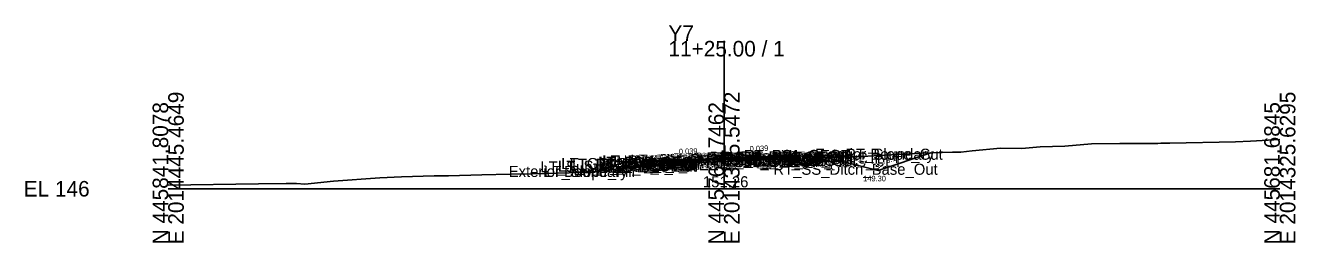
# Model space of a CAD drawing. Extents: x -26 to 203, y -10 to 7527.
# Drawn here: x -25.7 to 202.8, y 2490.3 to 2529.4 of the extents above; entities that cross this region are included whole.
import ezdxf

# ---------------------------------------------------------------- set-up
doc = ezdxf.new("R2010")
doc.units = 0
for name, color, linetype in [('Exist CMT Pavement', 7, 'Continuous'), ('Exist Cross Section Cell', 7, 'Continuous'), ('Exist XS Center Line Elevation Label', 7, 'Continuous'), ('Exist XS Ground Line', 7, 'Continuous'), ('Prop CMT Pvmt Course 1', 7, 'Continuous'), ('Prop CMT Pvmt Course 1 Wedge', 7, 'Continuous'), ('Prop CMT Pvmt Course 2', 7, 'Continuous'), ('Prop CMT Pvmt Course 2 Wedge', 7, 'Continuous'), ('Prop CMT Pvmt Course 3', 7, 'Continuous'), ('Prop CMT Pvmt Course 3 Wedge', 7, 'Continuous'), ('Prop CMT Pvmt Surface', 7, 'Continuous'), ('Prop CMT Pvmt Surface Shoulder', 7, 'Continuous'), ('Prop CMT Pvmt Wedge Surface 1', 7, 'Continuous'), ('Prop CMT Pvmt Wedge Surface 2', 7, 'Continuous'), ('Prop CMT Pvmt Wedge Surface 3', 7, 'Continuous'), ('Prop CMT Shld Paved Course 1', 7, 'Continuous'), ('Prop CMT Shld Paved Course 2', 7, 'Continuous'), ('Prop CMT Shld Paved Course 3', 7, 'Continuous'), ('Prop CMT Slope Grass', 7, 'Continuous'), ('Prop CMT Subgrade Earthwork', 7, 'Continuous'), ('Prop XS Ditch Standard Text', 7, 'Continuous'), ('Prop XS Earthwork Shape', 7, 'Continuous'), ('Prop XS SE Text', 7, 'Continuous'), ('Prop XS Side Slope Text', 7, 'Continuous'), ('Prop XS Wedging', 7, 'Continuous'), ('Scratch_Level_0', 7, 'Continuous')]:
    doc.layers.add(name, color=color, linetype=linetype)

msp = doc.modelspace()

# ---------------------------------------------------------------- linework, layer by layer
at = {"layer": 'Exist CMT Pavement'}
msp.add_lwpolyline([(93.3, 2505.03), (93.3, 2505.03), (93.89, 2505.04), (100, 2505.26), (100.81, 2505.28), (102.83, 2505.29), (107.59, 2505.3)], dxfattribs=at)
at = {"layer": 'Exist Cross Section Cell'}
for p, q in [((100, 2500), (100, 2526.62)), ((0, 2500), (100, 2500)), ((100, 2500), (200, 2500))]:
    msp.add_line(p, q, dxfattribs=at)
at = {"layer": 'Exist XS Ground Line'}
msp.add_lwpolyline([(0, 2500.67), (16.26, 2500.87), (21.22, 2500.96), (23.07, 2500.96), (24.6, 2500.84), (29.75, 2501.4), (38.09, 2501.97), (42, 2502.15), (47.86, 2502.31), (50.45, 2502.34), (56.42, 2502.49), (61.55, 2502.61), (65.4, 2502.71), (72.12, 2502.87), (75.6, 2502.95), (88.94, 2504.55), (91.24, 2504.8), (93.3, 2505.03), (93.89, 2505.04), (100, 2505.26), (100.81, 2505.28), (102.83, 2505.29), (107.59, 2505.3), (108.66, 2505.45), (111.02, 2505.83), (114.09, 2504.44), (114.73, 2504.22), (116.89, 2504.24), (118.03, 2505.23), (118.42, 2505.63), (124.81, 2505.79), (135.48, 2506.41), (141.1, 2506.6), (142.62, 2506.62), (144.65, 2506.82), (149.77, 2507.33), (153.59, 2507.28), (156.91, 2507.56), (161.35, 2507.7), (166.09, 2508.08), (171.2, 2508.13), (178.04, 2508.18), (178.58, 2508.19), (180.19, 2508.22), (192.01, 2508.44), (194.73, 2508.59), (200, 2508.87)], dxfattribs=at)
at = {"layer": 'Prop CMT Pvmt Course 1'}
for points in [[(100, 2505.51), (87.35, 2505.02)], [(87.35, 2505.02), (87.35, 2504.77)], [(87.35, 2504.77), (93.3, 2505)], [(93.3, 2505.12), (100, 2505.38)], [(93.3, 2505), (93.3, 2505.12)], [(100, 2505.51), (112.84, 2506)], [(107.59, 2505.67), (100, 2505.38)], [(100, 2505.26), (100, 2505.51)], [(100, 2505.26), (100, 2505.51)], [(100, 2505.38), (100, 2505.26), (100, 2505.26)], [(100, 2505.38), (100, 2505.26), (100, 2505.26)], [(112.84, 2505.75), (107.59, 2505.55)], [(107.59, 2505.55), (107.59, 2505.67)], [(112.84, 2506), (112.84, 2505.75)]]:
    msp.add_lwpolyline(points, dxfattribs=at)
at = {"layer": 'Prop CMT Pvmt Course 1 Wedge'}
for points in [[(100, 2505.38), (93.3, 2505.12)], [(100, 2505.38), (107.59, 2505.67)]]:
    msp.add_lwpolyline(points, dxfattribs=at)
at = {"layer": 'Prop CMT Pvmt Course 2'}
for points in [[(93.3, 2505), (87.35, 2504.77)], [(87.35, 2504.77), (87.35, 2504.43)], [(93.3, 2504.66), (93.3, 2505)], [(107.59, 2505.55), (112.84, 2505.75)], [(107.59, 2505.22), (107.59, 2505.55)], [(112.84, 2505.42), (107.59, 2505.22)], [(112.84, 2505.75), (112.84, 2505.42)], [(87.35, 2504.43), (93.3, 2504.66)]]:
    msp.add_lwpolyline(points, dxfattribs=at)
at = {"layer": 'Prop CMT Pvmt Course 2 Wedge'}
for points in [[(100, 2505.26), (93.3, 2505)], [(100, 2505.26), (107.59, 2505.55)]]:
    msp.add_lwpolyline(points, dxfattribs=at)
at = {"layer": 'Prop CMT Pvmt Course 3'}
for points in [[(107.59, 2505.22), (112.84, 2505.42)], [(107.59, 2504.88), (107.59, 2505.22)], [(112.84, 2505.08), (107.59, 2504.88)], [(112.84, 2505.42), (112.84, 2505.08)], [(93.3, 2504.66), (87.35, 2504.43)], [(87.35, 2504.43), (87.35, 2504.1)], [(87.35, 2504.1), (93.3, 2504.33)], [(93.3, 2504.33), (93.3, 2504.66)]]:
    msp.add_lwpolyline(points, dxfattribs=at)
at = {"layer": 'Prop CMT Pvmt Course 3 Wedge'}
for points in [[(100, 2504.92), (93.3, 2504.66)], [(100, 2504.92), (107.59, 2505.22)]]:
    msp.add_lwpolyline(points, dxfattribs=at)
at = {"layer": 'Prop CMT Pvmt Surface'}
for points in [[(100, 2505.51), (87.35, 2505.02)], [(100, 2505.51), (112.84, 2506)]]:
    msp.add_lwpolyline(points, dxfattribs=at)
at = {"layer": 'Prop CMT Pvmt Surface Shoulder'}
for points in [[(87.35, 2505.02), (87.35, 2505.02)], [(112.84, 2506), (112.84, 2506)]]:
    msp.add_lwpolyline(points, dxfattribs=at)
at = {"layer": 'Prop CMT Pvmt Wedge Surface 1'}
for points in [[(87.35, 2504.77), (87.35, 2505.02)], [(93.3, 2505), (87.35, 2504.77)], [(100, 2505.38), (93.3, 2505.12)], [(93.3, 2505.12), (93.3, 2505)], [(100, 2505.38), (107.59, 2505.67)], [(107.59, 2505.55), (112.84, 2505.75)], [(107.59, 2505.67), (107.59, 2505.55)], [(112.84, 2505.75), (112.84, 2506)]]:
    msp.add_lwpolyline(points, dxfattribs=at)
at = {"layer": 'Prop CMT Pvmt Wedge Surface 2'}
for points in [[(100, 2505.26), (87.35, 2504.77)], [(87.35, 2504.77), (87.35, 2505.02)], [(100, 2505.26), (112.84, 2505.75)], [(112.84, 2505.75), (112.84, 2506)]]:
    msp.add_lwpolyline(points, dxfattribs=at)
at = {"layer": 'Prop CMT Pvmt Wedge Surface 3'}
for points in [[(87.35, 2504.43), (87.35, 2505.02)], [(100, 2504.92), (87.35, 2504.43)], [(100, 2504.92), (112.84, 2505.42)], [(112.84, 2505.42), (112.84, 2506)]]:
    msp.add_lwpolyline(points, dxfattribs=at)
at = {"layer": 'Prop CMT Shld Paved Course 1'}
for points in [[(87.35, 2505.02), (87.09, 2504.76)], [(87.09, 2504.76), (87.35, 2504.77)], [(87.35, 2505.02), (87.35, 2505.02)], [(87.35, 2504.77), (87.35, 2505.02)], [(112.84, 2506), (112.84, 2506)], [(112.84, 2506), (113.09, 2505.75)], [(112.84, 2505.75), (112.84, 2506)], [(113.09, 2505.75), (112.84, 2505.75)]]:
    msp.add_lwpolyline(points, dxfattribs=at)
at = {"layer": 'Prop CMT Shld Paved Course 2'}
for points in [[(87.35, 2504.77), (87.09, 2504.76), (86.75, 2504.42)], [(87.35, 2504.43), (87.35, 2504.77)], [(112.84, 2505.75), (113.09, 2505.75), (113.43, 2505.41)], [(112.84, 2505.42), (112.84, 2505.75)], [(113.43, 2505.41), (112.84, 2505.42)], [(86.75, 2504.42), (87.35, 2504.43)]]:
    msp.add_lwpolyline(points, dxfattribs=at)
at = {"layer": 'Prop CMT Shld Paved Course 3'}
for points in [[(112.84, 2505.08), (112.84, 2505.42)], [(112.84, 2505.42), (113.43, 2505.41), (113.77, 2505.07)], [(114.27, 2505.06), (112.84, 2505.08)], [(85.91, 2504.07), (87.35, 2504.1)], [(87.35, 2504.43), (87.25, 2504.43), (86.75, 2504.42), (86.41, 2504.08)], [(87.35, 2504.1), (87.35, 2504.43)]]:
    msp.add_lwpolyline(points, dxfattribs=at)
at = {"layer": 'Prop CMT Slope Grass'}
for points in [[(87.35, 2505.02), (81.35, 2504.54), (77.12, 2503.13)], [(112.84, 2506), (118.84, 2505.52), (127.72, 2503.3)], [(127.72, 2503.3), (137.21, 2506.47)]]:
    msp.add_lwpolyline(points, dxfattribs=at)
at = {"layer": 'Prop CMT Subgrade Earthwork'}
for points in [[(93.3, 2504.33), (93.3, 2505.03)], [(107.59, 2504.88), (107.59, 2505.3)], [(107.59, 2504.88), (112.84, 2505.08)], [(112.84, 2505.08), (114.27, 2505.06)], [(114.27, 2505.06), (121.26, 2504.92)], [(85.91, 2504.07), (79.57, 2503.95)], [(87.35, 2504.1), (85.91, 2504.07)], [(93.3, 2504.33), (87.35, 2504.1)]]:
    msp.add_lwpolyline(points, dxfattribs=at)
at = {"layer": 'Prop XS Earthwork Shape'}
for points in [[(84.8, 2504.05), (88.94, 2504.55), (91.24, 2504.8), (93.3, 2505.03), (93.3, 2504.33), (87.35, 2504.1), (85.91, 2504.07)], [(107.59, 2504.88), (107.59, 2505.3), (108.66, 2505.45), (111.02, 2505.83), (112.68, 2505.08)], [(112.84, 2505.08), (114.27, 2505.06), (117.75, 2504.99), (116.89, 2504.24), (114.73, 2504.22), (114.09, 2504.44), (112.68, 2505.08)], [(117.75, 2504.99), (121.26, 2504.92), (118.84, 2505.52), (118.36, 2505.56), (118.03, 2505.23)], [(121.26, 2504.92), (127.72, 2503.3), (137.21, 2506.47), (135.48, 2506.41), (124.81, 2505.79), (118.42, 2505.63), (118.36, 2505.56), (118.84, 2505.52)], [(84.8, 2504.05), (79.57, 2503.95), (77.12, 2503.13)]]:
    msp.add_lwpolyline(points, close=True, dxfattribs=at)
at = {"layer": 'Prop XS Wedging'}
for p, q in [((100, 2505.38), (93.3, 2505.12)), ((93.3, 2505.12), (93.3, 2505.03)), ((93.3, 2505.03), (93.89, 2505.04)), ((93.89, 2505.04), (100, 2505.26)), ((107.59, 2505.67), (100, 2505.38)), ((106.67, 2505.51), (100, 2505.26)), ((100, 2505.38), (100, 2505.26)), ((100, 2505.26), (100, 2505.38)), ((102.83, 2505.29), (106.46, 2505.3)), ((106.46, 2505.3), (106.67, 2505.51)), ((106.46, 2505.3), (106.67, 2505.51)), ((106.67, 2505.51), (106.46, 2505.3)), ((106.46, 2505.3), (107.59, 2505.3)), ((107.59, 2505.55), (107.59, 2505.67)), ((107.59, 2505.3), (107.59, 2505.55))]:
    msp.add_line(p, q, dxfattribs=at)
for points in [[(100, 2505.26), (106.67, 2505.51), (107.59, 2505.55), (107.59, 2505.55)], [(100, 2505.26), (100.81, 2505.28), (102.83, 2505.29)], [(107.59, 2505.55), (106.67, 2505.51), (106.67, 2505.51)]]:
    msp.add_lwpolyline(points, dxfattribs=at)

# ---------------------------------------------------------------- texts
at = {"layer": 'Exist Cross Section Cell'}
for s, p in [('Y7', (90, 2526.62)), ('11+25.00 / 1', (90, 2523.82)), ('EL 146', (-26, 2498.6))]:
    msp.add_text(s, height=2.8, dxfattribs=at).set_placement(p)
for s, p in [('E 2014445.4649', (2.8, 2490)), ('E 2014385.5472', (102.8, 2490)), ('E 2014325.6295', (202.8, 2490)), ('N 445841.8078', (0, 2490)), ('N 445761.7462', (100, 2490)), ('N 445681.6845', (200, 2490))]:
    msp.add_text(s, height=2.8, rotation=90, dxfattribs=at).set_placement(p)
at = {"layer": 'Exist XS Center Line Elevation Label'}
msp.add_text('151.26', height=2, dxfattribs=at).set_placement((96.21, 2500.26))
at = {"layer": 'Prop XS Ditch Standard Text'}
msp.add_text('149.30', height=1, dxfattribs=at).set_placement((125.04, 2501.34))
at = {"layer": 'Prop XS SE Text'}
for rotation, p in [(2.2087, (91.9, 2506.19)), (2.2084, (104.64, 2506.69))]:
    msp.add_text('0.039', height=1, rotation=rotation, dxfattribs=at).set_placement(p)
at = {"layer": 'Prop XS Side Slope Text'}
for s, rotation, p in [('3:1', 18.4332, (78.24, 2504.29)), ('4:1', 345.9638, (122.25, 2505.44)), ('3:1', 18.4349, (129.3, 2504.54))]:
    msp.add_text(s, height=1, rotation=rotation, dxfattribs=at).set_placement(p)
at = {"layer": 'Scratch_Level_0'}
for s, p in [('RT_PV1_OEOT', (103.53, 2505)), ('RT_PS1_OEOP', (103.59, 2505)), ('Exterior Boundary', (116.37, 2505.22)), ('RT_Slope_Cut', (121.82, 2505.22)), ('LT_Sub_OSS_DLT', (66.97, 2502.95)), ('LT_Sub_Trench_Out', (70.12, 2503.07)), ('LT_GS_OS_CTL', (70.72, 2503.54)), ('LT_PS3_Shelf_Out', (72.24, 2503.41)), ('LT_PS3_OEOP', (76.99, 2503.42)), ('LT_PS2_OEOP', (77.33, 2503.76)), ('LT_Sub_OEOT', (77.43, 2503.1)), ('LT_PV2_OEOT', (77.52, 2503.77)), ('LT_PV3_OEOT', (77.52, 2503.43)), ('LT_PV1_OEOT', (78.09, 2504.02)), ('LT_PS1_OEOP', (78.15, 2504.02)), ('LT_Sub Tie Out', (80.64, 2504.03)), ('LT_PV_OEEOP_EG', (80.84, 2504.03)), ('LT_Sub_OEEOP', (82.51, 2503.33)), ('LT_PV2_OEEOP', (82.6, 2504)), ('LT_PV3_OEEOP', (82.6, 2503.66)), ('LT_PV1_OEEOP', (83.17, 2504.12)), ('RT_PV_IEEOP_EG', (88.14, 2504.25)), ('LT_PV_IEEOP_EG', (88.19, 2504.25)), ('RT_PV2_IEEOP', (89.91, 2504.26)), ('RT_PV3_IEEOP', (89.91, 2503.92)), ('LT_PV2_IEEOP', (89.95, 2504.26)), ('LT_PV3_IEEOP', (89.95, 2503.92)), ('RT_PV1_IEEOP', (90.47, 2504.38)), ('LT_PV1_IEEOP', (90.52, 2504.38)), ('PV2_PGL', (93.91, 2504.26)), ('PV1_PGL', (94.47, 2504.51)), ('RT_Sub Tie Out', (94.88, 2504.3)), ('RT_PV_OEEOP_EG', (95.08, 2504.3)), ('RT_Sub_OEEOP', (96.75, 2503.88)), ('RT_PV2_OEEOP', (96.85, 2504.55)), ('RT_PV3_OEEOP', (96.85, 2504.22)), ('RT_PV1_OEEOP', (97.42, 2504.67)), ('RT_Sub_Trench_Out', (98.43, 2504.06)), ('RT_PS3_Shelf_Out', (99.87, 2504.4)), ('RT_Sub_OEOT', (102.87, 2504.08)), ('RT_PV2_OEOT', (102.96, 2504.75)), ('RT_PV3_OEOT', (102.96, 2504.42)), ('RT_PS2_OEOP', (103.28, 2504.75)), ('RT_PS3_OEOP', (103.62, 2504.41)), ('RT_GS_OS_CTL', (108.16, 2504.52)), ('RT_Sub_OSS_DLT', (108.61, 2503.92)), ('Exterior Boundary', (61.26, 2502.13)), ('LT_Slope_Fill', (67.64, 2502.13)), ('RT_SS_Ditch_Base_Out', (108.87, 2502.52))]:
    msp.add_text(s, height=2, dxfattribs=at).set_placement(p)

doc.saveas('drawing.dxf')
